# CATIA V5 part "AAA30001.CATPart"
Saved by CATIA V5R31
Part number: AAA30001
Revision: 3
Nomenclature: PLATE
Source: Unknown
Property "部品番号(A社)": "AAA30001"
Property "部品名称(A社)": "PLATE"
Property "Version(A社)": "3"
Property "材質": "JSH270C"
Property "板厚": "4"
Bounding box of the stored display mesh (mm): x -15 to 15, y -15 to 15, z 0 to 4
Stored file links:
  \\cad-nas02\CATIA1212\BODY_DEPARTMENT8\JAMA\変換データ\STEP3_最終_20240115\01_いすゞ板金\new_ファイル名修正後\CATIA_V5_20240122\AAA30001.CATPart
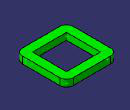
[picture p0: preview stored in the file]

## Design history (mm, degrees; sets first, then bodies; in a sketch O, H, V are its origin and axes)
Set1
  DatumPoint1 to DatumPoint4
Body1 "MANIFOLD_SOLID_BREP #327" (main body)
  Solid1: solid without history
